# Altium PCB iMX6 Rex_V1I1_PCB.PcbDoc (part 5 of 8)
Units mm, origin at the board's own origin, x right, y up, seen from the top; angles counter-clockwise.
Board outline 70 x 40 mm, 12 copper layers (L1, L2, L3, L4, L5 (PWR), L6 (PWR), L7 (PWR), L8 (PWR), L9, L10, L11, L12), stack 1.566 mm thick; 473 components, 409 nets, 2294 pads, 1880 vias.
Unrouted connection lines stored in the file: 7.
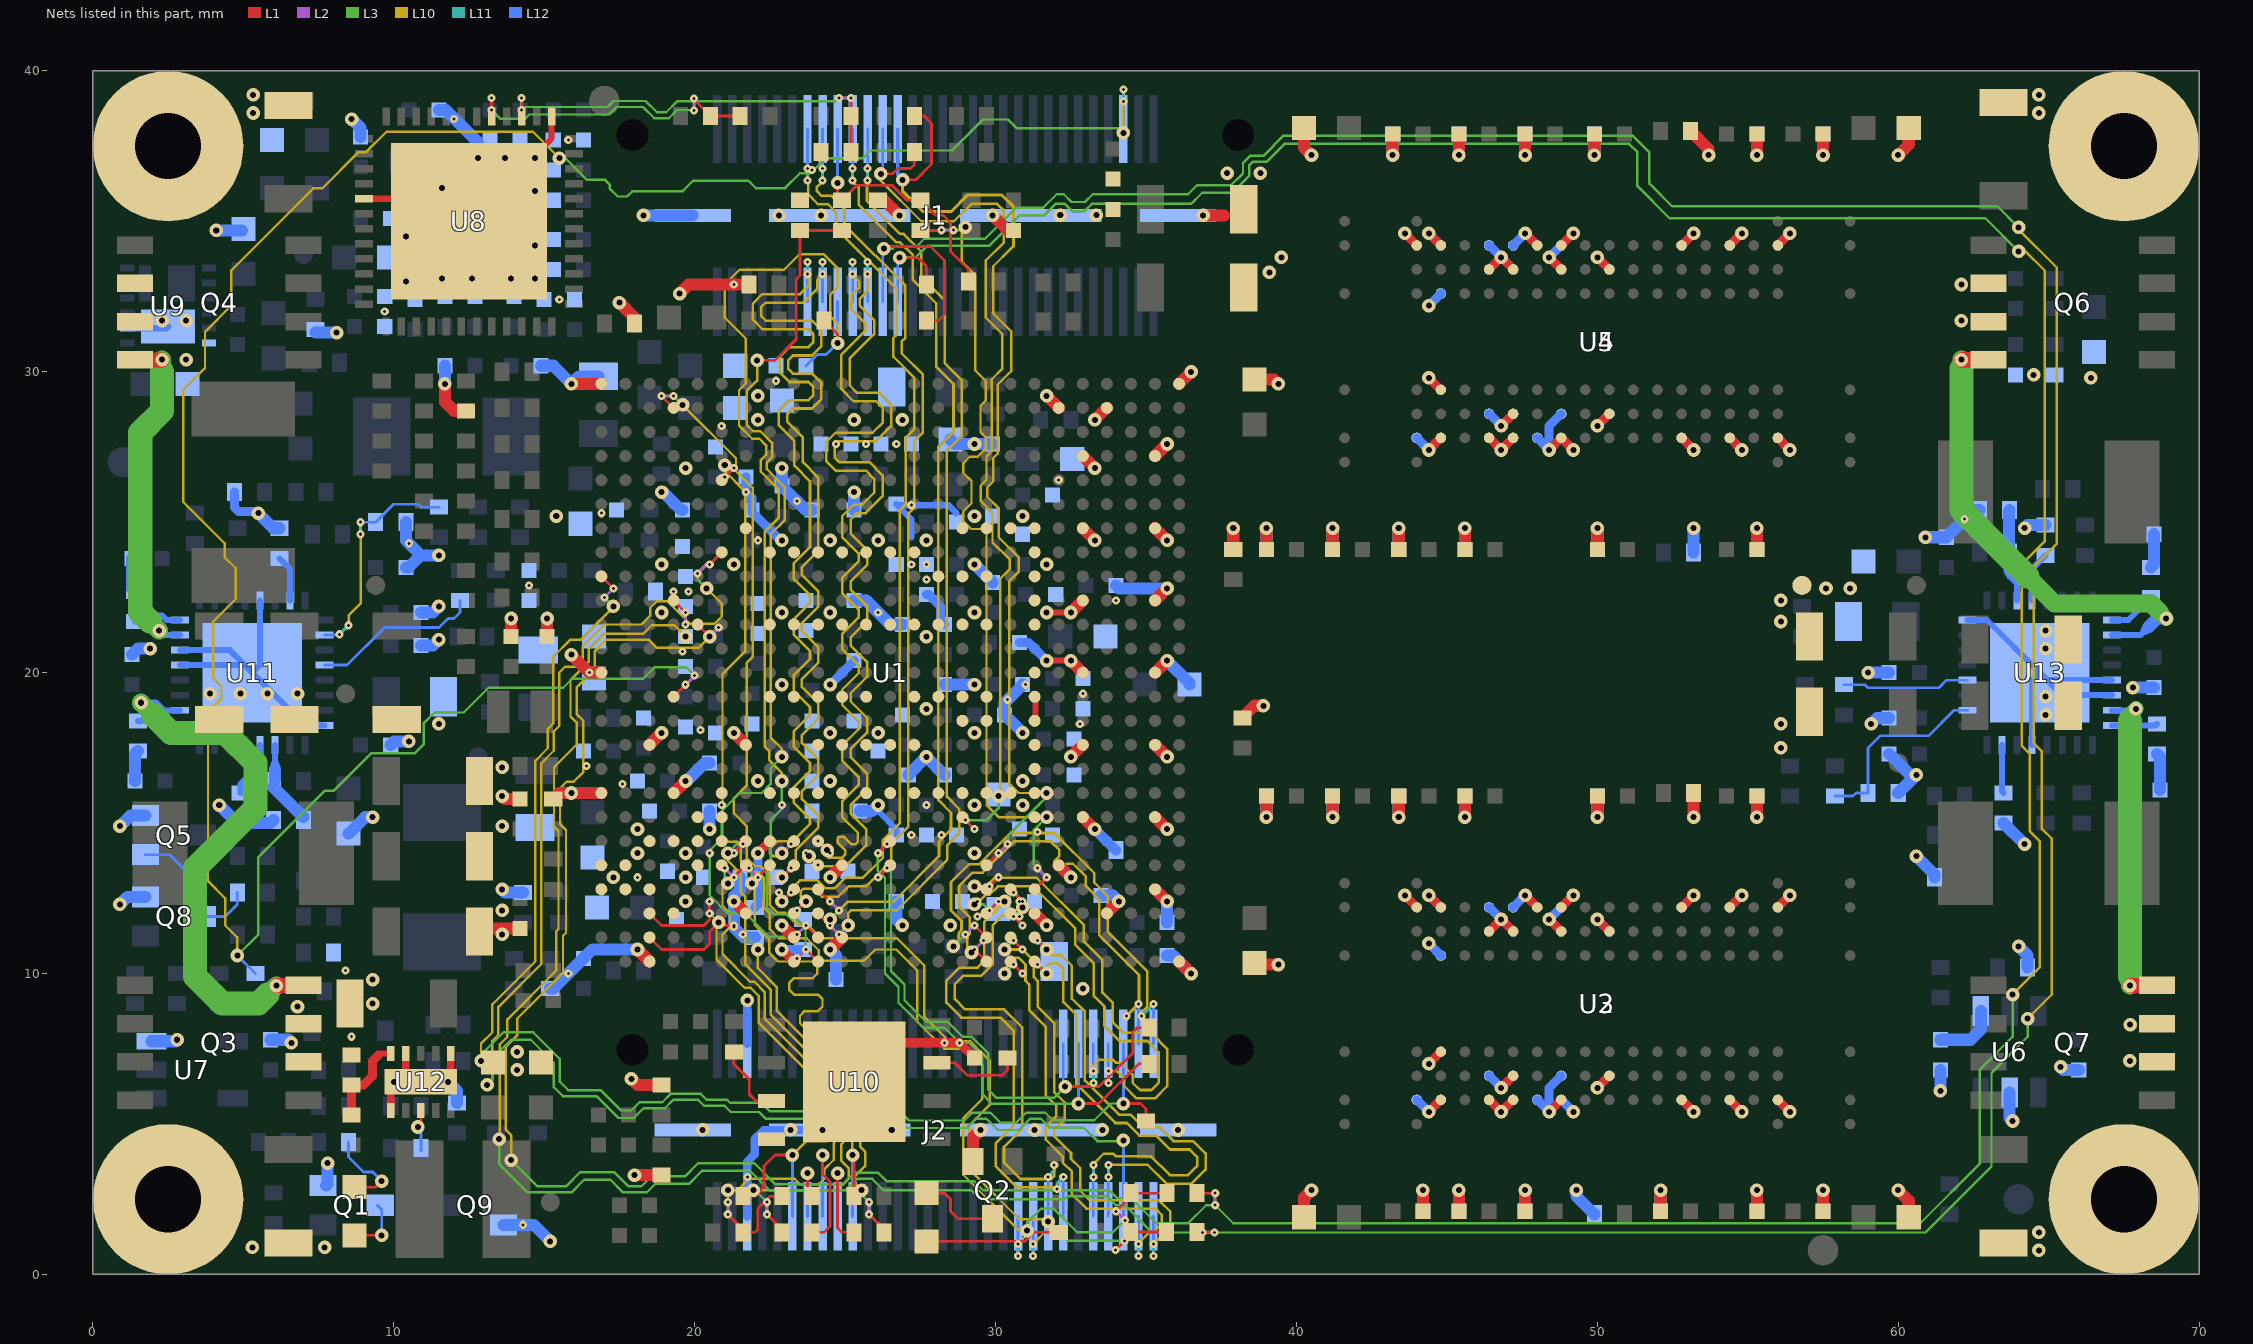
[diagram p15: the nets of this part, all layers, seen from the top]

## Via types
v1: diameter 0.45, hole 0.2, L1 to L12, tented both sides, 761 vias
v2: diameter 0.27, hole 0.1, L1 to L2, 305 vias
v3: diameter 0.27, hole 0.1, L2 to L3, 290 vias
v4: diameter 0.45, hole 0.2, L3 to L10, 196 vias
v5: diameter 0.27, hole 0.1, L11 to L12, 185 vias
v6: diameter 0.27, hole 0.1, L10 to L11, 142 vias
v7: diameter 0.45, hole 0.2, L3 to L10, tented both sides, 1 vias

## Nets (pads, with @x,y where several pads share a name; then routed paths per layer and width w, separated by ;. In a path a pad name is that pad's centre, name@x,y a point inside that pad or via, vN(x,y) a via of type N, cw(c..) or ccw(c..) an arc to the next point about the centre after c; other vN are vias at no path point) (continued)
FB1_2V5: R147.1 R150.2 U13.11 | length 3.1
  L12 w0.2: 63.7,23.3 63.7,23.2 63.95,22.95 U13.11@63.95,22.4
  L12 w0.3: 63.7,23.3 63.7,23.4
  L12 w0.4: 63.7,23.4 R147.1@63.7,24 63.675,24.025 63.675,25.375 R150.2@63.7,25.4
FB1_3V3: R123.1 R126.2 U11.11 | length 2.6
  L12 w0.2: 6.05,16.95 U11.11@6.05,17.6
  L12 w0.3: 6.05,16.8 6.05,16.95
  L12 w0.4: R123.1@6,16.2 R126.2@7,15.2 ; R123.1@6.05,16.45 6.05,16.8
FB_3V0_SNVS: R138.1 R139.2 U12.5 | length 3
  L1 w0.2: 9.5,7.3 9.55,7.35 U12.5@9.9,7.35
  L1 w0.3: R138.1@8.6,5.3 R139.2@8.6,6.3 9,6.3 9.3,6.6 9.3,7.1 9.5,7.3
GND: C1.2 C2.2 C3.2 C4.2 C5.2 C6.2 C7.2 C8.2 C9.2 C10.2 C11.2 C12.2 C13.2 C14.2 C15.2 C16.2 C17.2 C19.2 C20.2 C21.2 C22.2 C23.2 C24.2 C25.2 C26.2 C27.2 C28.2 C29.2 C30.2 C31.2 C32.2 C33.2 C34.2 C35.2 C36.2 C37.2 C38.2 C39.2 C40.2 C41.2 C42.2 C43.2 C44.2 C45.2 C46.2 C47.2 C48.2 C49.2 C50.2 C51.2 C52.2 C53.2 C54.2 C55.2 C56.2 C57.2 C58.2 C59.2 C60.2 C61.2 C62.2 C64.2 C68.2 C73.2 C74.1 C75.2 C76.2 C77.2 C78.2 C79.2 C80.2 C81.2 C82.2 C83.2 C84.2 C85.2 C86.2 C87.2 C88.2 C89.2 C90.2 C91.2 C92.2 C93.2 C94.2 C95.2 C96.2 C97.2 C98.2 C99.2 C100.2 C101.2 C102.2 C103.2 C104.2 C105.2 C106.2 C107.2 C108.2 C109.2 C110.2 C111.2 C112.2 C113.2 C114.2 C115.2 C116.2 C117.2 C118.2 C119.2 C120.2 C121.2 C122.2 C123.2 C124.2 C125.2 C126.2 C127.2 C128.2 C129.2 C130.2 C131.2 C132.2 C133.2 C134.2 C135.2 C136.2 C137.2 C138.2 C139.1 C140.2 C141.2 C142.2 C143.2 C144.2 C145.2 C146.2 C147.2 C148.2 C149.2 C150.2 C151.2 C152.2 C153.2 C154.2 C155.2 C156.2 C157.2 C158.2 C159.2 C160.2 C161.2 C162.2 C163.2 C164.2 C165.2 C166.2 C167.2 C168.2 C169.2 C170.2 C171.2 C172.2 C173.2 C174.2 C175.2 C176.2 C177.2 C178.2 C180.2 C181.2 C182.2 C183.2 C184.2 C185.2 C186.2 C187.2 C188.2 C189.2 C190.2 C191.2 C192.2 C193.2 C194.2 C195.2 C196.2 C197.2 C198.2 C199.2 C200.2 C201.2 C202.2 C203.2 C204.2 C205.2 C206.2 C207.2 C208.2 C209.2 C210.2 C213.2 C214.2 C215.2 C216.2 C217.2 C218.2 C219.2 C220.2 C221.2 C222.2 C223.2 C224.2 C225.2 C226.2 C227.2 C228.2 C229.2 C232.2 C233.2 C234.2 C235.2 C236.2 C237.2 C238.2 C239.2 C240.2 C241.2 C242.2 C243.2 C244.2 C245.2 C246.2 C247.2 C248.2 C249.2 J1.61 J1.62 J1.63 J1.64 J2.55 J2.56 J2.61 J2.62 J2.63 J2.64 MH1.1 MH2.1 MH3.1 MH4.1 Q1.2 Q2.2 Q3.2 Q3.3 Q4.2 Q4.3 Q5.2 Q6.2 Q6.3 Q7.2 Q7.3 Q8.2 Q9.2 R4.1 R5.1 R6.1 R7.1 R8.1 R9.1 R10.2 R12.1 R15.1 R16.1 R17.1 R20.1 R26.1 R30.1 R37.2 R56.1 R57.1 R58.1 R61.1 R67.1 R79.1 R84.2 R99.1 R101.1 R102.1 R124.2 R125.1 R126.1 R133.1 R136.1 R139.1 R143.1 R144.1 R148.2 R149.1 R150.1 R155.1 R158.1 TP10.1 U1.A4 U1.A5 U1.A8 U1.A13 U1.A25 U1.AA7 U1.AA10 U1.AA13 U1.AA16 U1.AA19 U1.AA22 U1.AB3 U1.AB24 U1.AD4 U1.AD7 U1.AD10 U1.AD13 U1.AD16 U1.AD19 U1.AD22 U1.AE1 U1.AE25 U1.B4 U1.B5 U1.C1 U1.C4 U1.C6 U1.C10 U1.D3 U1.D6 U1.D8 U1.E5 U1.E6 U1.E7 U1.F5 U1.F6 U1.F7 U1.F8 U1.G3 U1.G10 U1.G19 U1.H8 U1.H12 U1.H15 U1.H18 U1.J2 U1.J8 U1.J12 U1.J15 U1.J18 U1.K8 U1.K10 U1.K12 U1.K15 U1.K18 U1.L2 U1.L5 U1.L8 U1.L10 U1.L12 U1.L15 U1.L18 U1.M8 U1.M10 U1.M12 U1.M15 U1.M18 U1.N8 U1.N10 U1.N15 U1.N18 U1.P8 U1.P10 U1.P12 U1.P15 U1.P18 U1.R8 U1.R12 U1.R15 U1.R17 U1.T8 U1.T11 U1.T12 U1.T15 U1.T17 U1.T19 U1.U8 U1.U11 U1.U12 U1.U15 U1.U17 U1.U19 U1.V8 U1.V19 U1.W3 U1.W7 U1.W8 U1.W9 U1.W10 U1.W11 U1.W12 U1.W13 U1.W15 U1.W16 U1.W17 U1.W18 U1.W19 U1.Y5 U1.Y24 U2.A9 U2.B1 U2.B3 U2.B9 U2.D1 U2.D8 U2.E1 U2.E2 U2.E8 U2.F9 U2.G1 U2.G8 U2.G9 U2.J2 U2.J8 U2.M1 U2.M9 U2.P1 U2.P9 U2.T1 U2.T9 U3.A9 U3.B1 U3.B3 U3.B9 U3.D1 U3.D8 U3.E1 U3.E2 U3.E8 U3.F9 U3.G1 U3.G8 U3.G9 U3.J2 U3.J8 U3.M1 U3.M9 U3.P1 U3.P9 U3.T1 U3.T9 U4.A9 U4.B1 U4.B3 U4.B9 U4.D1 U4.D8 U4.E1 U4.E2 U4.E8 U4.F9 U4.G1 U4.G8 U4.G9 U4.J2 U4.J8 U4.M1 U4.M9 U4.P1 U4.P9 U4.T1 U4.T9 U5.A9 U5.B1 U5.B3 U5.B9 U5.D1 U5.D8 U5.E1 U5.E2 U5.E8 U5.F9 U5.G1 U5.G8 U5.G9 U5.J2 U5.J8 U5.M1 U5.M9 U5.P1 U5.P9 U5.T1 U5.T9 U6.2 U7.3 U8.13 U8.29 U8.49 U9.2 U9.12 U9.13 U10.4 U10.9 U11.8 U11.21 U11.22 U11.29 U11.33 U12.1 U12.4 U12.6 U12.11 U13.8 U13.21 U13.22 U13.29 U13.33 | length 250
  L1 w0.2: U8.29@9.01,35.75 U8.49@10.2,35.75 ; U8.49@14.65,37.15 15.25,37.75 U8.13@15.25,38.49 ; U1.W11@31.3,18.4 31.325,18.425 31.325,19.175 U1.W12@31.3,19.2 ; v1(31.7,20.4) v1(32.5,20.4) ; v1(31.7,22) v1(32.5,22)
  L1 w0.25: U12.6@9.9,5.35 9.9,6.3 v1(10,6.4) ; U12.11@10.4,6.2 U12.4@10.4,7.25 ; U12.11@11.9,6.4 U12.1@11.9,7.25
  L1 w0.3: U10.9@25.3,6.4 26.6,7.7 v2(28.8,7.7) C203.2@29.3,7.2 ; v1(43.6,12.6) U2.A9@44,12.2 ; v1(43.6,34.6) U4.A9@44,34.2 ; v1(44.4,5.4) U2.B1@44.8,5.8 ; v1(44.4,7) U2.B3@44.8,7.4 ; v1(44.4,12.6) U2.B9@44.8,12.2 ; v1(44.4,27.4) U4.B1@44.8,27.8 ; v1(44.4,29.8) U4.B3@44.8,29.4 ; v1(44.4,34.6) U4.B9@44.8,34.2 ; U2.D1@46.4,5.8 v1(46.8,5.4) U2.E1@47.2,5.8 ; U2.D8@46.4,11.4 v1(46.8,11.8) U2.E8@47.2,11.4 ; U4.D1@46.4,27.8 v1(46.8,27.4) U4.E1@47.2,27.8 ; U4.D8@46.4,33.4 v1(46.8,33.8) U4.E8@47.2,33.4 ; v1(46.8,6.2) U2.E2@47.2,6.6 ; v1(46.8,28.2) U4.E2@47.2,28.6 ; v1(47.6,12.6) U2.F9@48,12.2 ; v1(47.6,34.6) U4.F9@48,34.2 ; v1(48.4,5.4) U2.G1@48.8,5.8 ; v1(48.4,11.8) U2.G8@48.8,11.4 ; v1(48.4,27.4) U4.G1@48.8,27.8 ; v1(48.4,33.8) U4.G8@48.8,33.4 ; U2.G9@48.8,12.2 v1(49.2,12.6) ; U4.G1@48.8,27.8 v1(49.2,27.4) ; U4.G9@48.8,34.2 v1(49.2,34.6) ; v1(50,6.2) U2.J2@50.4,6.6 ; v1(50,11.8) U2.J8@50.4,11.4 ; v1(50,28.2) U4.J2@50.4,28.6 ; v1(50,33.8) U4.J8@50.4,33.4 ; U2.M1@52.8,5.8 v1(53.2,5.4) ; U2.M9@52.8,12.2 v1(53.2,12.6) ; U4.M1@52.8,27.8 v1(53.2,27.4) ; U4.M9@52.8,34.2 v1(53.2,34.6) ; U2.P1@54.4,5.8 v1(54.8,5.4) ; U2.P9@54.4,12.2 v1(54.8,12.6) ; U4.P1@54.4,27.8 v1(54.8,27.4) ; U4.P9@54.4,34.2 v1(54.8,34.6) ; U2.T1@56,5.8 v1(56.4,5.4) ; U2.T9@56,12.2 v1(56.4,12.6) ; U4.T1@56,27.8 v1(56.4,27.4) ; U4.T9@56,34.2 v1(56.4,34.6)
  L1 w0.4: v1(11.7,29.6) 11.7,29 12,28.7 R99.1@12.4,28.7 ; C215.2@13.2,11.5 C84.2@14.2,11.5 ; v1(13.6,15.9) 13.7,15.8 C83.2@14.2,15.8 ; C86.2@13.9,21.2 v1(13.9,21.8) ; C85.2@15.1,21.2 v1(15.1,21.8) ; R37.2@15.3,15.8 15.5,16 v1(15.9,16) U1.A8@16.9,16 ; v1(15.9,20.6) v2(16.5,20) U1.A13@16.9,20 ; v1@15.9,29.6 U1.A25@16.9,29.6 ; v1(17.5,32.3) 18,31.8 R84.2@18,31.6 ; v1(17.9,6.5) 18.1,6.3 R16.1@18.9,6.3 ; v1(18,3.3) R17.1@18.9,3.3 ; v1(18.1,10.8) U1.C1@18.5,10.4 ; U1.C10@18.5,17.6 v1(18.9,18) ; U1.D8@19.3,16 v1(19.7,16.4) ; v1(19.5,32.6) 19.8,32.9 v2(21.3,32.9) R143.1@21.8,32.9 ; v1(21.3,12.4) U1.G3@21.7,12 ; v1(21.3,18) U1.G10@21.7,17.6 ; v1(22.9,11.6) U1.J2@23.3,11.2 ; v1(24.5,10.8) U1.L2@24.9,11.2 ; v1(24.5,13.2) U1.L5@24.9,13.6 ; R144.1@26.1,35.7 26.3,35.7 v1(26.8,35.2) ; Q2.2@29.25,3.75 29.25,4.55 v1(29.5,4.8) ; v1(29.9,35.2) 30.4,34.7 C242.2@30.6,34.7 ; U1.W3@31.3,12 v1(31.7,11.6) ; v1(31.7,29.2) U1.Y24@32.1,28.8 ; U1.Y5@32.1,13.6 v1(32.5,13.2) ; v1(32.5,17.2) U1.AA10@32.9,17.6 ; v1(32.5,20.4) U1.AA13@32.9,20 ; v1(32.5,22) U1.AA16@32.9,22.4 ; U1.AA7@32.9,15.2 v1(33.3,14.8) ; U1.AA19@32.9,24.8 v1(33.3,24.4) ; U1.AA22@32.9,27.2 v1(33.3,26.8) ; v1(33.3,28.4) U1.AB24@33.7,28.8 ; U1.AB3@33.7,12 v1(34.1,12.4) ; U1.AD4@35.3,12.8 v1(35.7,12.4) ; U1.AD7@35.3,15.2 v1(35.7,14.8) ; U1.AD10@35.3,17.6 v1(35.7,17.2) ; U1.AD13@35.3,20 v1(35.7,20.4) ; U1.AD16@35.3,22.4 v1(35.7,22.8) ; U1.AD19@35.3,24.8 v1(35.7,24.4) ; U1.AD22@35.3,27.2 v1(35.7,27.6) ; U1.AE1@36.1,10.4 v1(36.5,10) ; U1.AE25@36.1,29.6 v1(36.5,30) ; v1(36.9,35.2) 37.6,35.2 ; R10.2@37.9,24.1 v1(37.9,24.8) ; R6.1@38.2,18.5 38.6,18.9 v1@38.8,18.9 ; C12.2@38.6,10.35 38.65,10.3 v1(39.4,10.3) ; C17.2@38.6,29.75 39.25,29.75 v1(39.4,29.6) ; v1(39,15.2) C26.2@39,15.9 ; C39.2@39,24.1 v1(39,24.8) ; C14.2@40.25,1.9 40.25,2.55 v1(40.5,2.8) ; C15.2@40.25,38.1 40.25,37.45 v1(40.5,37.2) ; v1(41.2,15.2) C24.2@41.2,15.9 ; C40.2@41.2,24.1 v1(41.2,24.8) ; v1(43.2,37.2) C36.2@43.2,37.9 ; v1(43.4,15.2) C25.2@43.4,15.9 ; C31.2@43.4,24.1 v1(43.4,24.8) ; C27.2@44.2,2.1 v1(44.2,2.8) ; C28.2@45.4,2.1 v1(45.4,2.8) ; v1(45.4,37.2) C37.2@45.4,37.9 ; v1(45.6,15.2) C23.2@45.6,15.9 ; C33.2@45.6,24.1 v1(45.6,24.8) ; C29.2@47.6,2.1 v1(47.6,2.8) ; v1(47.6,37.2) C34.2@47.6,37.9 ; v1(49.9,37.2) C8.2@49.9,37.9 ; v1(50,15.2) C3.2@50,15.9 ; C9.2@50,24.1 v1(50,24.8) ; C4.2@52.1,2.1 v1(52.1,2.8) ; R8.1@53.1,38 53.7,37.4 v1(53.7,37.2) ; v1(53.2,15.2) R4.1@53.2,16 ; C30.2@55.3,2.1 v1(55.3,2.8) ; v1(55.3,15.2) C22.2@55.3,15.9 ; C32.2@55.3,24.1 v1(55.3,24.8) ; v1(55.3,37.2) C38.2@55.3,37.9 ; C21.2@57.5,2.1 v1(57.5,2.8) ; v1(57.5,37.2) C35.2@57.5,37.9 ; v1(60,2.8) 60.35,2.45 C13.2@60.35,1.9 ; v1(60,37.2) 60.35,37.55 C16.2@60.35,38.1
  L12 w0.2: U11.21@2.9,20.25 U11.33@5.05,20.25 ; U11.22@2.9,20.75 4.55,20.75 U11.33@5.05,20.25 ; U11.29@5.55,22.4 5.55,20.25 U11.33@5.3,20 ; U11.8@7.7,18.25 7.05,18.25 U11.33@5.3,20 ; v1(26.1,15.6) 26.1,15.401 26.7,14.801 C107.2@26.7,14.6 ; U13.8@62.3,21.75 62.95,21.75 U13.33@64.7,20 ; U13.29@64.45,17.6 64.45,19.75 U13.33@64.7,20 ; U13.22@67.1,19.25 65.45,19.25 U13.33@64.95,19.75 ; U13.21@67.1,19.75 U13.33@64.95,19.75 ; U11.33@5.05,20.25 U11.33@5.3,20 ; U13.33@64.7,20 U13.33@64.95,19.75
  L12 w0.22: U9.2@1.14,31.45 2.448,31.45 U9.13@2.5,31.501 ; C130.2@26.7,25.6 C130.2@26.735,25.565 ; 27.2,24.5 27.2,25.1 C130.2@26.735,25.565 ; 28.7,25.3 28.435,25.565 C130.2@26.735,25.565
  L12 w0.28: J2.55@21.75,1.93 21.75,3.75 21.994,3.994 21.994,4.494 22.3,4.8 J2.63@24.825,4.8 ; J2.56@21.75,7.67 v1(21.75,9.108)
  L12 w0.3: R136.1@4.7,26 4.7,25.5 4.85,25.35 5.45,25.35 v1(5.5,25.3) ; C125.2@21.7,26.5 v5(21.7,26) 21.9,25.8 C122.2@21.9,25.4 21.9,25.346 22.846,24.4 v1(22.9,24.4) ; v1(24.5,19.6) C94.2@25.3,20.4 ; C113.2@27.7,22.6 27.772,22.6 28.175,22.197 28.175,21.725 C97.2@28.3,21.6 ; C117.2@30.8,21 31.1,21 v1(31.7,20.4) ; U3.A9@44,5.8 v1(44.4,5.4) U3.B9@44.8,5.8 ; U5.A9@44,27.8 v1(44.4,27.4) U5.B9@44.8,27.8 ; v1(44.4,11) U3.B3@44.8,10.6 ; v1(44.4,12.6) U3.B1@44.8,12.2 ; v1(44.4,32.2) U5.B3@44.8,32.6 ; v1(44.4,34.6) U5.B1@44.8,34.2 ; U3.D8@46.4,6.6 v1(46.8,6.2) U3.E8@47.2,6.6 ; U3.D1@46.4,12.2 U3.E2@47.2,11.4 ; U5.D8@46.4,28.6 v1(46.8,28.2) U5.E8@47.2,28.6 ; U5.D1@46.4,34.2 v1(46.8,33.8) U5.E2@47.2,33.4 ; U3.E1@47.2,12.2 v1(47.6,12.6) ; U5.E1@47.2,34.2 v1(47.6,34.6) ; U3.F9@48,5.8 v1(48.4,5.4) 48.4,6.2 U3.G8@48.8,6.6 ; U5.F9@48,27.8 v1(48.4,27.4) 48.4,28.2 U5.G8@48.8,28.6 ; v1(48.4,11.8) U3.G1@48.8,12.2 ; v1(48.4,33.8) U5.G1@48.8,34.2 ; U3.G9@48.8,5.8 v1(49.2,5.4) ; U5.G9@48.8,27.8 v1(49.2,27.4) ; v1(50,6.2) U3.J8@50.4,6.6 ; v1(50,11.8) U3.J2@50.4,11.4 ; v1(50,28.2) U5.J8@50.4,28.6 ; v1(50,33.8) U5.J2@50.4,33.4 ; U3.M9@52.8,5.8 v1(53.2,5.4) ; U3.M1@52.8,12.2 v1(53.2,12.6) ; U5.M9@52.8,27.8 v1(53.2,27.4) ; U5.M1@52.8,34.2 v1(53.2,34.6) ; U3.P9@54.4,5.8 v1(54.8,5.4) ; U3.P1@54.4,12.2 v1(54.8,12.6) ; U5.P9@54.4,27.8 v1(54.8,27.4) ; U5.P1@54.4,34.2 v1(54.8,34.6) ; U3.T9@56,5.8 v1(56.4,5.4) ; U3.T1@56,12.2 v1(56.4,12.6) ; U5.T9@56,27.8 v1(56.4,27.4) ; U5.T1@56,34.2 v1(56.4,34.6)
  L12 w0.35: v1(33.3,14.8) R7.1@34,14.1
  L12 w0.4: v1(0.9,12.3) 1.15,12.55 Q8.2@1.75,12.55 ; v1(0.9,14.9) 1.25,15.25 Q5.2@1.75,15.25 ; C206.2@1.3,20.6 1.5,20.8 v1(1.9,20.8) ; U7.3@1.95,7.75 2.75,7.75 v1(2.8,7.8) ; v1(4.1,34.7) C178.2@4.95,34.7 ; v1(4.2,15.6) R125.1@4.8,15 ; R125.1@4.9,15 5.9,15 R126.1@6,15.1 ; v1(5.5,25.3) 6,24.8 R124.2@6.2,24.8 ; C89.2@5.9,7.8 6.5,7.8 v1(6.6,7.7) ; R101.1@7.4,31.3 v1(8.1,31.3) ; Q1.2@7.75,2.95 7.8,3 v1(7.8,3.7) ; C204.2@8.5,14.65 9.05,15.2 v1(9.3,15.2) ; v1(8.6,38.4) 8.9,38.1 C184.2@8.9,37.8 ; C205.2@9.9,17.6 10.014,17.714 v1(10.5,17.714) ; C219.2@10.4,23.5 10.5,23.5 10.9,23.9 ; R133.1@10.4,25 10.4,24.4 10.9,23.9 ; C218.2@10.9,20.9 11.3,20.9 v1(11.5,21.1) ; C207.2@10.9,22 11.3,22 v1(11.5,22.2) ; v1(11.5,23.9) 10.9,23.9 ; C249.2@11.5,38.7 11.727,38.7 12.8,37.627 v1(12.8,37.1) ; v1(11.6,36.1) C186.2@12.3,35.4 ; v1(11.7,29.6) C176.2@11.7,30.2 ; v1(11.8,6.4) 12.1,6.1 R58.1@12.1,5.7 ; C186.2@12.35,35.4 C186.2@12.45,35.4 ; v1(13.6,12.8) 13.7,12.7 R79.1@14.3,12.7 ; Q9.2@13.65,1.65 14.65,1.65 v1(15.2,1.1) ; C175.2@14.9,30.2 15.3,30.2 v1(15.9,29.6) 16.15,29.85 C148.2@16.8,29.85 ; R15.1@15.2,9.5 15.3,9.5 C244.2@16.3,10.5 16.6,10.8 v1(18.1,10.8) ; v1(18.3,35.2) J1.64@19.935,35.2 ; v1(18.9,26) 18.958,26 19.558,25.4 C152.2@19.6,25.4 ; v1(19.7,16.4) 19.735,16.4 20.335,17 C139.1@20.5,17 ; v1(20.5,14.8) C143.2@20.5,15.4 ; C61.2@21.5,13.2 21.5,12.774 21.3,12.574 v1(21.3,12.4) v5(21.3,11.542) 21.642,11.2 R61.1@22,11.2 ; v1(22.9,26.8) C131.2@22.9,26.2 23.7,25.4 C134.2@23.9,25.4 ; v1(24.5,10.8) 24.7,10.6 C1.2@24.7,9.8 ; C124.2@25.3,22.4 25.7,22.4 26.5,21.6 C95.2@26.9,21.6 ; C133.2@25.3,25.4 v1(25.3,26) ; C90.2@25.5,15.4 25.9,15.4 v1(26.1,15.6) ; C76.2@26.7,12.4 26.7,11.8 v1(26.9,11.6) ; C116.2@27.1,16.6 v1(27.7,17.2) C115.2@28.3,16.6 ; C105.2@28.3,19.6 v1(29.3,19.6) ; C129.2@28.5,27.75 28.65,27.6 v1(29.3,27.6) C160.2@29.9,27.6 ; v1(29.3,23.6) C114.2@29.9,23 ; v1(30.9,18) C102.2@30.3,18.6 30.3,19 C112.2@30.9,19.6 ; C243.2@33.5,12.6 33.9,12.6 v1(34.1,12.4) ; C171.2@34,22.9 34.1,22.8 v1(35.7,22.8) ; C245.2@35.7,10.6 35.9,10.6 v1(36.5,10) ; C7.2@35.7,11.7 v1(35.7,12.4) ; v1(35.7,20.4) 36.45,19.65 C172.2@36.45,19.6 ; v1(39,15.2) C46.2@39,15.9 ; C60.2@39,24.1 v1(39,24.8) ; v1(41.2,15.2) C43.2@41.2,15.9 ; C51.2@41.2,24.1 v1(41.2,24.8) ; v1(43.2,37.2) C57.2@43.2,37.9 ; v1(43.4,15.2) C45.2@43.4,15.9 ; C53.2@43.4,24.1 v1(43.4,24.8) ; C47.2@44.2,2.1 v1(44.2,2.8) ; C49.2@45.4,2.1 v1(45.4,2.8) ; v1(45.4,37.2) C56.2@45.4,37.9 ; v1(45.6,15.2) C44.2@45.6,15.9 ; C52.2@45.6,24.1 v1(45.6,24.8) ; C48.2@47.6,2.1 v1(47.6,2.8) ; v1(47.6,37.2) C59.2@47.6,37.9 ; v1(49.3,2.8) 49.3,2.6 R5.1@49.9,2 ; v1(49.9,37.2) C10.2@49.9,37.9 ; v1(50,15.2) C5.2@50,15.9 ; C11.2@50,24.1 v1(50,24.8) ; C6.2@52.1,2.1 v1(52.1,2.8) ; R9.1@53.2,24 v1(53.2,24.8) ; C50.2@55.3,2.1 v1(55.3,2.8) ; v1(55.3,15.2) C42.2@55.3,15.9 ; C54.2@55.3,24.1 v1(55.3,24.8) ; v1(55.3,37.2) C58.2@55.3,37.9 ; C41.2@57.5,2.1 v1(57.5,2.8) ; v1(57.5,37.2) C55.2@57.5,37.9 ; v1(59,20) C237.2@59.7,20 ; v1(59.1,18.3) 59.3,18.5 C226.2@59.7,18.5 ; C238.2@59.7,17.3 60.4,16.6 v1(60.6,16.6) R155.1@60,16 ; v1(60.6,13.9) 61.2,13.3 R158.1@61.2,13.2 ; v1(60.9,24.5) C224.2@61.6,24.5 62.5,25.4 R150.1@62.7,25.4 ; v1(61.4,6.1) C88.2@61.4,6.8 ; R148.2@63.5,15 v1(64.2,14.3) ; U6.2@63.7,6.05 63.7,5.2 v1(63.8,5.1) ; v1(64,10.9) 64.3,10.6 R67.1@64.3,10.2 ; v1(64.2,24.8) 64.3,24.9 R149.1@64.9,24.9 ; v1(65.4,6.9) 65.5,6.8 C87.2@66,6.8 ; v1(67.8,19.5) C225.2@68.5,19.5
  other v1: 64.675,0.8 5.3,0.9 7.7,0.9 64.675,1.4 20.263,4.805 23.187,4.805 24.25,4.805 26.55,4.805 31.3,4.8 33.55,4.805 36.065,4.8 14.1,6.8 67.7,7.1 14.1,7.4 67.705,8.3 6.8,8.9 9.3,9 32.9,9.5 9.3,9.8 13.6,11.3 28.5,11.6 13.6,12.1 19.7,12.4 17.3,13.2 19.7,13.2 18.1,14 19.7,14 29.3,14 18.1,14.8 13.6,14.9 29.3,15.6 30.9,15.6 22.1,16.4 24.5,16.4 30.9,16.4 13.6,16.85 56.1,17.5 24.5,18 26.1,18 29.3,18 11.5,18.3 56.1,18.3 64.9,18.6 27.7,18.8 38.9,18.9 64.9,19.2 3.9,19.3 4.9,19.3 5.8,19.3 6.8,19.3 22.9,19.6 64.9,20.8 27.7,21.2 64.9,21.4 56.1,21.7 18.9,22 22.9,22 24.5,22 29.3,22 56.1,22.4 57.6,22.8 58.4,22.8 18.9,23.6 21.3,23.6 31.7,23.6 24.5,24.4 26.1,24.4 27.7,24.4 15.4,25.2 29.3,25.2 30.9,25.2 19.7,26.8 22.1,28.4 25.3,28.4 26.9,28.4 22.1,29.2 66.4,29.8 64.5,29.9 3.1,30.4 2.3,31.7 3.1,31.7 62.1,31.7 62.1,32.9 10.4,33 11.6,33.1 12.6,33.1 13.9,33.1 14.7,33.1 39.1,33.3 39.5,33.8 14.7,34.2 10.4,34.5 22.8,35.2 24.2,35.2 32.15,35.205 33.35,35.205 14.7,36 37.7,36.6 38.8,36.6 13.7,37.1 14.7,37.1 5.325,38.6 64.675,38.6 5.325,39.2 64.675,39.2
  other v2: 28.3,7.7 8.6,7.9 18.1,13.2 20.5,14 20.9,15.6 22.9,15.6 27.7,15.6 31,19.6 26.1,22 27.7,23.6 22.1,24.4 23.9,36.7
  other v5: 14.3,1.65 21.75,3.243 15.8,10 8.4,10.1 29.4,11.9 30.8,11.9 29.4,12.4 30.8,12.4 22.8,12.7 27.2,14.6 28.2,14.6 31.4,14.7 17.6,16.3 16.4,16.9 20.2,18.1 32.8,18.3 30.4,19.1 32.9,19.3 19.6,20.7 26.1,22 34,22.4 19.3,22.7 19.8,22.7 14.5,22.9 27.7,23.1 27.2,23.6 10.5,24.3 62.2,25.1 16.9,25.3 27.2,25.565 23.4,25.7 32.1,26.4 24.7,27.6 25.7,27.6 26.7,27.6 20.9,28.2 22.7,29.7 9.7,32 15.5,32.4 15.8,37.7 12,38.4
HDMI_CEC: R25.1 U1.W4 | length 27.5
  L1 w0.093: R25.1@27.6,34.7 28.195,34.7 v2(28.2,34.705) ; U1.W4@31.3,12.8 v2(31.7,13.2)
  L2 w0.1: v2(28.2,34.705) v3(28.6,34.705) ; v3(31.4,13.5) v2(31.7,13.2)
  L3 w0.08: v3(28.6,34.705) 28.9,34.705 v4(29,34.805) ; v3(31.4,13.5) 31.275,13.625 31.275,14.775 v4(31.7,15.2)
  L10 w0.08: v4(29,34.805) 28.875,34.68 28.875,33.665 29.325,33.215 29.325,30.045 29.675,29.695 29.675,29.045 29.5,28.87 29.5,28 29.675,27.825 29.675,27.445 29.405,27.175 29.145,27.175 28.925,26.955 28.925,26.645 29.2,26.37 29.2,25.63 28.925,25.355 28.925,25.045 29.195,24.775 29.525,24.775 29.7,24.6 29.7,15.6 30.1,15.2 v4(31.7,15.2)
HDMI_CEC_IN: J1.44 R22.1 R24.2 R25.2 | length 9
  L1 w0.093: v1(24.75,36.28) 24.75,35.85 R24.2@24.9,35.7 25.4,36.2 26.562,36.2 27.062,35.7 R25.2@27.5,35.7 27.995,35.205 28.25,35.205 28.5,34.955 28.5,34 29.1,33.4 R22.1@29.1,33
  L12 w0.093: v1(24.75,36.28) J1.44@24.75,38.07
HDMI_CLK_N: J1.45 U1.J5 | length 32.2
  L1 w0.09: v2(22.9,13.2) U1.J5@23.3,13.6
  L2 w0.1: v2(22.9,13.2) v3(23.2,13.5)
  L3 w0.085: v2(22.9,13.2) v3(23.2,13.5)
  L10 w0.085: v2(22.9,13.2) 23.363,13.663 23.363,14.103 24.114,14.854 24.114,15.252 23.566,15.8 23.566,16.066 24.114,16.614 24.114,17.112 23.566,17.66 23.566,17.926 24.114,18.474 24.114,18.972 23.566,19.52 23.566,19.786 24.114,20.334 24.114,20.832 23.566,21.38 23.566,21.646 24.114,22.194 24.114,22.692 23.566,23.24 23.566,23.506 24.114,24.054 24.114,26.476 23.595,26.995 23.595,27.817 23.08,28.332 23.08,28.598 23.262,28.78 23.9,28.78 24.214,29.094 24.214,29.626 23.9,29.94 23.262,29.94 23.112,30.09 23.112,30.39 23.262,30.54 23.9,30.54 24.214,30.854 24.214,31.386 23.9,31.7 22.362,31.7 22.212,31.85 22.212,32.15 22.362,32.3 23.616,32.3 24.08,32.764 24.08,33.046 24.25,33.216 v6(24.25,33.242)
  L11 w0.1: v6(24.25,33.242) v5(24.25,33.642)
  L12 w0.09: J1.45@24.25,32.33 v5(24.25,33.642)
  other v4: 22.9,13.2
HDMI_CLK_P: J1.47 U1.J6 | length 32.2
  L1 w0.09: v4(22.9,14) U1.J6@23.3,14.4
  L2 w0.1: v4(22.9,14) v3(23.2,14.3)
  L3 w0.085: v4(22.9,14) v3(23.2,14.3)
  L10 w0.085: v4(22.9,14) 22.8,13.9 22.6,13.9 22.5,14 22.5,14.15 22.75,14.4 23.264,14.4 23.834,14.97 23.834,15.136 23.286,15.684 23.286,16.182 23.834,16.73 23.834,16.996 23.286,17.544 23.286,18.042 23.834,18.59 23.834,18.856 23.286,19.404 23.286,19.902 23.834,20.45 23.834,20.716 23.286,21.264 23.286,21.762 23.834,22.31 23.834,22.576 23.286,23.124 23.286,23.622 23.834,24.17 23.834,26.36 23.315,26.879 23.315,27.701 22.8,28.216 22.8,28.714 23.146,29.06 23.784,29.06 23.934,29.21 23.934,29.51 23.784,29.66 23.146,29.66 22.832,29.974 22.832,30.506 23.146,30.82 23.784,30.82 23.934,30.97 23.934,31.27 23.784,31.42 22.246,31.42 21.932,31.734 21.932,32.266 22.246,32.58 23.5,32.58 23.8,32.88 23.8,33.192 v6(23.75,33.242)
  L11 w0.1: v6(23.75,33.242) v5(23.75,33.642)
  L12 w0.09: J1.47@23.75,32.33 v5(23.75,33.642)
  other v2: 22.9,14
HDMI_D0_N: J1.39 U1.K5 | length 32.1
  L1 w0.09: v2(23.7,14) v3(24.1,13.6)
  L2 w0.1: v2(23.7,14) v3(24.1,13.6)
  L3 w0.085: v4(23.8,13.9) v3(24.1,13.6)
  L10 w0.085: v4(23.8,13.9) 24.132,13.568 25.013,13.568 25.7,14.254 25.7,14.8 25.182,15.318 25.182,15.596 25.73,16.144 25.73,16.642 25.182,17.19 25.182,17.456 25.73,18.004 25.73,18.502 25.182,19.05 25.182,19.316 25.73,19.864 25.73,20.362 25.182,20.91 25.182,21.176 25.73,21.724 25.73,22.222 25.182,22.77 25.182,23.036 25.73,23.584 25.73,24.082 25.182,24.63 25.182,25.082 25.4,25.3 25.68,25.3 26.244,25.864 26.244,26.556 25.806,26.994 24.802,26.994 24.652,27.144 24.652,27.544 24.802,27.694 26.03,27.694 26.532,28.197 26.532,28.916 26.148,29.3 25.4,29.3 25.148,29.552 25.148,30.437 25.964,31.254 25.964,31.716 25.48,32.2 25.48,32.414 25.75,32.684 v6(25.75,33.242)
  L11 w0.1: v6(25.75,33.242) v5(25.75,33.642)
  L12 w0.09: J1.39@25.75,32.33 v5(25.75,33.642)
HDMI_D0_P: J1.41 U1.K6 | length 32.1
  L1 w0.09: v3(24.1,14.4) v2(24.5,14)
  L2 w0.1: v3(24.1,14.4) v2(24.5,14)
  L3 w0.085: v3(24.1,14.4) v4(24.4,14.1)
  L10 w0.085: v4(24.4,14.1) 24.4,13.898 24.45,13.848 24.897,13.848 25,13.95 25,14.1 24.75,14.35 24.75,14.5 24.8,14.55 24.95,14.55 25.2,14.3 25.35,14.3 25.42,14.37 25.42,14.684 24.902,15.202 24.902,15.712 25.45,16.26 25.45,16.526 24.902,17.074 24.902,17.572 25.45,18.12 25.45,18.386 24.902,18.934 24.902,19.432 25.45,19.98 25.45,20.246 24.902,20.794 24.902,21.292 25.45,21.84 25.45,22.106 24.902,22.654 24.902,23.152 25.45,23.7 25.45,23.966 24.902,24.514 24.902,25.198 25.284,25.58 25.564,25.58 25.964,25.98 25.964,26.44 25.69,26.714 24.686,26.714 24.372,27.028 24.372,27.66 24.686,27.974 25.914,27.974 26.252,28.312 26.252,28.8 26.032,29.02 25.284,29.02 24.868,29.437 24.868,30.553 25.684,31.37 25.684,31.6 25.2,32.084 25.2,32.53 25.47,32.8 25.47,32.996 25.25,33.216 v6(25.25,33.242)
  L11 w0.1: v6(25.25,33.242) v5(25.25,33.642)
  L12 w0.09: J1.41@25.25,32.33 v5(25.25,33.642)
HDMI_D1_N: J1.46 U1.J3 | length 32.1
  L1 w0.09: U1.J3@23.3,12 v4(23.7,12.4)
  L2 w0.1: v3(23.4,12.1) v4(23.7,12.4)
  L3 w0.085: v3(23.4,12.1) v4(23.7,12.4)
  L10 w0.085: v4(23.7,12.4) 23.523,12.577 23.523,12.727 23.616,12.82 23.964,12.82 24.232,12.552 24.768,12.552 25.116,12.9 25.7,12.9 26.532,13.732 26.532,14.317 27.1,14.884 27.1,25.284 27.3,25.484 27.3,27.704 27.582,27.986 27.582,29.914 26.88,30.616 26.88,31 27,31.12 27,32.86 24.98,34.88 24.98,35.416 24.548,35.848 24.216,35.848 24.06,36.004 24.06,36.14 24.25,36.331 v6(24.25,36.357)
  L11 w0.1: v6(24.25,36.357) v5(24.25,36.758)
  L12 w0.09: v5(24.25,36.758) J1.46@24.25,38.07
  other v2: 23.7,12.4
HDMI_D1_P: J1.48 U1.J4 | length 32.1
  L1 w0.09: v2(22.9,12.4) U1.J4@23.3,12.8
  L2 w0.1: v2(22.9,12.4) v3(23.2,12.7)
  L3 w0.085: v2(22.9,12.4) v3(23.2,12.7)
  L10 w0.085: v2(22.9,12.4) 23.243,12.743 23.243,12.843 23.5,13.1 24.08,13.1 24.348,12.832 24.652,12.832 25,13.18 ; v6(23.75,36.357) 23.78,36.328 23.78,35.888 24.1,35.568 24.432,35.568 24.7,35.3 24.7,34.764 26.72,32.744 26.72,31.236 26.6,31.116 26.6,30.5 27.302,29.798 27.302,28.102 27.02,27.82 27.02,25.6 26.82,25.4 26.82,15 26.252,14.433 26.252,13.848 25.584,13.18 25,13.18
  L11 w0.1: v6(23.75,36.357) v5(23.75,36.758)
  L12 w0.09: v5(23.75,36.758) J1.48@23.75,38.07
  other v4: 22.9,12.4
HDMI_D2_N: J1.40 U1.K3 | length 32.1
  L1 w0.09: U1.K3@24.1,12 v2(24.5,11.6)
  L2 w0.1: v2(24.5,11.6) v3(24.8,11.3)
  L3 w0.085: v3(24.8,11.3) v4(25.1,11.6)
  L10 w0.085: v4(25.1,11.6) 25.1,12.004 25.196,12.1 26.716,12.1 28.4,13.784 28.4,14.266 28.8,14.666 28.8,15.46 28.38,15.88 28.38,27.384 28.882,27.886 28.882,29.714 28.308,30.288 28.308,32.392 27.53,33.17 27.53,33.991 26.941,34.58 26.825,34.58 25.728,35.677 25.728,36.335 v6(25.75,36.357)
  L11 w0.1: v6(25.75,36.357) v5(25.75,36.758)
  L12 w0.09: v5(25.75,36.758) J1.40@25.75,38.07
HDMI_D2_P: J1.42 U1.K4 | length 32.1
  L1 w0.09: U1.K4@24.1,12.8 v2(24.5,12.4)
  L2 w0.1: v2(24.5,12.4) v3(24.8,12.1)
  L3 w0.085: v4(24.5,11.8) v3(24.8,12.1)
  L10 w0.085: v4(24.5,11.8) 25.08,12.38 26.6,12.38 28.12,13.9 28.12,14.382 28.52,14.782 28.52,15.344 28.1,15.764 28.1,27.5 28.602,28.002 28.602,29.598 28.028,30.172 28.028,32.277 27.25,33.054 27.25,33.875 26.825,34.3 26.709,34.3 25.448,35.561 25.448,36.133 25.25,36.331 v6(25.25,36.357)
  L11 w0.1: v6(25.25,36.357) v5(25.25,36.758)
  L12 w0.09: v5(25.25,36.758) J1.42@25.25,38.07
HDMI_DDC: R24.1 R26.2 U1.K2 | length 31.7
  L1 w0.093: v1(22.075,30.38) 22.675,30.38 23.375,31.08 23.375,33.075 23.5,33.2 R26.2@23.5,34.7 R24.1@24.9,34.7 ; v2(23.7,11.6) U1.K2@24.1,11.2
  L2 w0.1: v3(23.4,11.3) v2(23.7,11.6)
  L3 w0.08: v4(22.9,17.2) 22.525,16.825 22.525,16.295 22.23,16 21.5,16 20.9,15.4 20.9,14.485 20.5,14.085 20.5,12.6 21.1,12 21.7,12 22.475,11.225 23.325,11.225 v3(23.4,11.3)
  L10 w0.08: v1(22.075,30.38) 22.075,29.705 21.725,29.355 21.725,28.245 21.945,28.025 22.188,28.025 22.575,27.638 22.575,27.162 22.4,26.987 22.4,26.758 23,26.158 23,25.075 22.525,24.6 22.525,17.845 22.9,17.47 v4(22.9,17.2)
HDMI_HPD: C74.2 J1.43 R21.1 U1.K1 | length 37
  L1 w0.093: v2(23.7,10.8) U1.K1@24.1,10.4 ; R21.1@24.3,31.7 24.75,31.25 v1(24.75,30.955)
  L2 w0.1: v3(23.4,10.5) v2(23.7,10.8)
  L3 w0.08: v4(22.9,16.4) 22.9,15.475 22.525,15.1 22.525,13.7 22.4,13.575 22.4,12.2 22.625,11.975 23.055,11.975 23.215,11.815 23.385,11.815 23.685,11.515 23.685,10.785 v3(23.4,10.5)
  L10 w0.08: v4(22.9,16.4) 22.9,16.67 22.475,17.095 22.475,17.4 22.325,17.55 22.325,24.683 22.8,25.158 22.8,26.075 22.2,26.675 22.2,27.07 22.375,27.245 22.375,27.555 22.155,27.775 21.912,27.775 21.475,28.212 21.475,29.388 21.7,29.613 21.7,31.1 21,31.8 21,32.9 21.492,33.392 22.968,33.392 23.475,33.9 24.3,33.9 24.75,33.45 24.75,32.8 24.5,32.55 24.5,31.85 24.75,31.6 v1(24.75,30.955)
  L12 w0.101: C74.2@23.7,30.2 24.076,30.576 24.371,30.576 v1(24.75,30.955) ; v1(24.75,30.955) J1.43@24.75,32.33
HDMI_RESREF: R30.2 U1.J1 | length 1.3
  L1 w0.3: v1(22.9,10.8) U1.J1@23.3,10.4
  L12 w0.3: v1(22.9,10.8) R30.2@23.6,10.8
I2C1_SCL: J2.14 R47.1 U1.N5 | length 18.6
  L1 w0.093: v2(26.1,13.2) U1.N5@26.5,13.6 ; v1(32.313,6.242) 33.438,6.242 34.563,7.367 34.563,8.055 34.707,8.2 R47.1@35.1,8.2
  L2 w0.1: v2(26.1,13.2) v3(26.4,13.5)
  L3 w0.08: v3(26.4,13.5) 26.525,13.375 26.525,10.088 26.975,9.638 26.975,9.113 27.688,8.4 28.4,8.4 28.9,7.9 29.2,7.9 29.763,7.337 29.763,6.137 30.032,5.867 31.938,5.867 v1(32.313,6.242)
  L12 w0.093: J2.14@32.25,7.67 32.25,6.305 v1(32.313,6.242)
I2C1_SDA: J2.12 R46.1 U1.N6 | length 19.7
  L1 w0.093: v2(26.1,14) U1.N6@26.5,14.4 ; v1(32.75,5.68) 33.438,5.68 34.758,7 R46.1@35.1,7
  L2 w0.1: v2(26.1,14) v3(26.4,14.3)
  L3 w0.08: v3(26.4,14.3) 26.085,13.985 26.085,13.412 26.325,13.172 26.325,10.005 26.775,9.555 26.775,9.03 27.605,8.2 28.3,8.2 28.8,7.7 29.117,7.7 29.563,7.255 29.563,5.993 29.888,5.667 32.737,5.667 v1(32.75,5.68)
  L12 w0.101: v1(32.75,5.68) J2.12@32.75,7.67
I2C2_SCL: J1.36 R28.1 U1.U5 | length 34.9
  L1 w0.093: v1(26.912,36.38) 27.35,36.38 27.875,36.905 27.875,38.255 27.63,38.5 R28.1@27.3,38.5 ; U1.U5@29.7,13.6 v2(30.1,14)
  L2 w0.1: v2(30.1,14) v3(30.4,14.3)
  L3 w0.08: v3(30.4,14.3) 30.4,14.57 31.43,15.6 31.7,15.87 v4(31.7,16)
  L10 w0.08: 30.5,34.08 29.925,33.505 29.925,31.938 30.517,31.346 30.517,30.017 30.075,29.575 30.075,27.279 29.925,27.129 29.925,26.355 29.725,26.155 29.725,25.845 30.1,25.47 30.1,24.5 30.775,23.825 30.775,23.362 30.45,23.037 30.45,16.32 30.77,16 v4(31.7,16)
  L10 w0.101: v1(26.912,36.38) 26.912,36.001 27.584,35.33 28.53,35.33 29.08,35.88 30.2,35.88 30.6,35.48 30.6,34.18 30.5,34.08
  L12 w0.101: J1.36@26.75,38.07 26.75,36.542 v1(26.912,36.38)
I2C2_SDA: J1.38 R29.1 U1.T7 | length 31.8
  L1 w0.093: v1(26.188,36.58) 26.58,36.58 26.755,36.755 27.175,36.755 27.3,36.88 R29.1@27.3,37.3 ; U1.T7@28.9,15.2 v2(29.3,14.8)
  L2 w0.1: v3(29,15.1) v2(29.3,14.8)
  L3 w0.08: v3(29,15.1) 29.7,15.1 30.1,15.5 v4(30.1,15.9)
  L10 w0.08: v1(26.188,36.58) 26.188,36.343 27.53,35 28.62,35 29.2,35.58 30.05,35.58 30.275,35.355 30.275,34.3 29.675,33.7 29.675,31.805 30.217,31.263 30.217,30.092 29.875,29.75 29.875,27.362 29.7,27.187 29.7,26.413 29.508,26.221 29.508,25.7 29.9,25.308 29.9,24.33 30.475,23.755 30.475,23.445 30.15,23.12 30.15,15.95 v4(30.1,15.9)
  L12 w0.093: v1(26.188,36.58) 26.25,36.642 J1.38@26.25,38.07
I2C3_SCL: J2.19 R31.1 R157.2 U1.F21 | length 44.4
  L1 w0.093: U1.F21@20.9,26.4 v2(21.3,26.8) ; v2(34,2.1) 34.5,2.6 R31.1@34.5,2.7 R157.2@35.7,2.7
  L2 w0.1: v3(21,26.5) v2(21.3,26.8) ; v2(34,2.1) v3(34.3,1.8)
  L3 w0.08: v3(21,26.5) v4(21,26.9) ; v4(31.05,1.458) 31.05,1.73 31.5,2.18 31.938,2.18 32.718,1.4 33.9,1.4 v3(34.3,1.8)
  L10 w0.08: v4(21,26.9) 21,26.7 21.675,26.025 21.675,20.7 20.925,19.95 20.925,14.575 21.125,14.375 21.425,14.375 21.525,14.275 21.525,13.762 21.912,13.375 22.1,13.375 22.3,13.175 22.3,12.187 22.493,11.993 22.493,11.476 22.795,11.175 23.725,11.175 24.125,10.775 24.125,10.6 24.3,10.425 25.625,10.425 26,10.8 26.7,10.8 27.4,10.1 27.4,8.4 28.3,7.5 29.022,7.5 29.563,6.96 29.563,5.838 28.925,5.2 28.925,3.313 30.78,1.458 v4(31.05,1.458) 31.05,1.318 v6(30.75,1.018)
  L11 w0.1: v5(30.75,0.617) v6(30.75,1.018)
  L12 w0.093: v5(30.75,0.617) J2.19@30.75,1.93
I2C3_SDA: J2.17 R32.1 R156.2 U1.D24 | length 45.4
  L1 w0.093: v2(18.9,29.2) U1.D24@19.3,28.8 ; v2(33.987,0.808) 34.487,1.308 R32.1@34.487,1.408 R156.2@35.687,1.408
  L2 w0.1: v2(18.9,29.2) v3(19.3,29.2) ; v2(33.987,0.808) v3(34.287,1.107)
  L3 w0.08: v3(19.3,29.2) v4(19.6,28.9) ; v4(31.75,1.758) 32.39,1.118 34.277,1.118 v3(34.287,1.107)
  L10 w0.08: v4(19.6,28.9) 21.375,27.125 21.375,26.695 21.925,26.145 21.925,20.525 21.725,20.325 21.725,16.245 21.3,15.82 21.3,15.33 21.725,14.905 21.725,13.845 21.995,13.575 22.183,13.575 22.5,13.258 22.5,12.27 22.745,12.025 23.005,12.025 23.43,11.6 23.775,11.6 24.2,11.175 26.725,11.175 27.625,10.275 27.625,8.575 28.45,7.75 29.155,7.75 29.813,7.093 29.813,5.643 29.125,4.955 29.125,4.645 29.285,4.485 29.285,3.336 30.788,1.833 31.675,1.833 v4(31.75,1.758) 31.75,1.518 v6(31.25,1.018)
  L11 w0.1: v5(31.25,0.617) v6(31.25,1.018)
  L12 w0.093: v5(31.25,0.617) J2.17@31.25,1.93
I2C4_SCL: J1.35 R45.1 R157.1 U1.E15 | length 154.3
  L1 w0.093: U1.E15@20.1,21.6 v2(20.5,21.2) ; v1(26.813,33.793) 27.412,33.793 27.7,33.505 R45.1@27.7,32.9 ; R157.1@36.7,2.7 v2@37.292,2.7
  L2 w0.1: v2(20.5,21.2) v3(20.8,21.5) ; v3(37.3,2.3) v2(37.3,2.7)
  L3 w0.08: v4(13.9,3.8) 14.775,2.925 15.725,2.925 16.2,3.4 17.325,3.4 17.8,2.925 18.225,2.925 18.559,3.259 19.676,3.259 20.117,3.7 21.983,3.7 22.69,2.993 24.93,2.993 25.312,3.375 26.1,3.375 26.375,3.1 29.283,3.1 29.583,2.8 33.783,2.8 34.041,2.541 34.5,2.541 35.341,1.7 36.4,1.7 37,2.3 v3(37.3,2.3) 37.9,1.7 60.73,1.7 62.715,3.685 62.715,6.815 63.8,7.9 v4(63.8,9.3) ; v2(20.5,21.2) v3(20.8,21.5) ; v1(26.813,33.793) 27.338,33.793 27.74,34.195 29.795,34.195 30.805,35.205 31.625,35.205 31.775,35.355 31.775,35.36 31.995,35.58 32.305,35.58 32.555,35.33 32.945,35.33 33.195,35.58 36.5,35.58 36.87,35.95 37.863,35.95 38.425,36.512 38.425,36.855 38.545,36.975 39,36.975 39.6,37.575 51.055,37.575 51.33,37.3 51.33,36.17 52.4,35.1 62.9,35.1 v4(64,34)
  L10 w0.08: v4(13.9,3.8) 13.9,4.63 13.725,4.805 13.725,7.567 14.1,7.942 14.1,8.5 15.625,10.025 15.625,11.255 15.725,11.355 15.725,14.775 15.525,14.975 15.525,16.155 15.745,16.375 15.975,16.375 16.3,16.7 16.3,18.4 16.075,18.625 16.075,19.505 16.675,20.105 16.675,20.705 17.07,21.1 18.47,21.1 18.745,20.825 20.125,20.825 v2(20.5,21.2) ; v4(63.8,9.3) 64.7,10.2 64.7,14.4 64.375,14.725 64.375,17.3 64.1,17.575 64.1,23.6 64.875,24.375 64.875,33.355 64.23,34 v4(64,34)
  L12 w0.093: J1.35@26.75,32.33 26.75,33.73 v1(26.813,33.793)
  other v4: 20.5,21.2
I2C4_SDA: J1.37 R44.1 R156.1 U1.D16 | length 158.7
  L1 w0.093: U1.D16@19.3,22.4 v2(19.7,22) ; v1(26.288,34.093) 26.363,34.168 27.832,34.168 28.3,33.7 28.3,31.9 28.1,31.7 R44.1@27.7,31.7 ; R156.1@36.687,1.408 v2@37.267,1.408
  L2 w0.1: v3(19.7,21.6) v2(19.7,22) ; v3(36.88,1.395) v2(37.28,1.395)
  L3 w0.08: v4(13.5,4.5) 13.5,3.67 14.445,2.725 15.908,2.725 16.333,3.15 17.192,3.15 17.617,2.725 18.408,2.725 18.692,3.009 19.809,3.009 20.25,3.45 21.83,3.45 22.487,2.793 25.013,2.793 25.395,3.175 25.9,3.175 26.275,2.8 29.2,2.8 29.5,2.5 32.3,2.5 32.4,2.6 33.7,2.6 34,2.3 34.3,2.3 35.205,1.395 v3(36.88,1.395) 60.908,1.395 63.1,3.587 63.1,6.7 64.3,7.9 v4(64.3,8.5) ; v4(19.7,21.2) v3(19.7,21.6) ; v1(26.288,34.093) 26.582,34.093 26.657,34.168 27.38,34.168 27.632,34.42 29.65,34.42 30.685,35.455 31.587,35.455 32.032,35.9 32.268,35.9 32.526,35.643 32.974,35.643 33.232,35.9 36.4,35.9 36.7,36.2 37.83,36.2 38.225,36.595 38.225,36.938 38.462,37.175 38.9,37.175 39.575,37.85 51.163,37.85 51.73,37.283 51.73,36.253 52.483,35.5 63.3,35.5 v4(64,34.8)
  L10 w0.08: v4@13.525,4.5 13.525,7.65 13.775,7.9 13.775,8.475 15.4,10.1 15.4,11.4 15.475,11.475 15.475,14.742 15.325,14.892 15.325,16.855 16.075,17.605 16.075,18.342 15.875,18.542 15.875,19.762 16.475,20.362 16.475,20.788 16.987,21.3 18.3,21.3 18.575,21.575 19.325,21.575 v4(19.7,21.2) ; v4(64,34.8) 64,34.73 65.275,33.455 65.275,24.292 64.5,23.517 64.5,17.658 64.775,17.383 64.775,14.808 65.1,14.483 65.1,9.3 v4(64.3,8.5)
  L12 w0.093: J1.37@26.25,32.33 26.25,34.055 v1(26.288,34.093)
JTAG_MOD: R61.2 U1.H6 | length 2.4
  L1 w0.3: v1(22.1,14) U1.H6@22.5,14.4
  L12 w0.3: R61.2@22,12.2 22.1,12.3 v1(22.1,14)
JTAG_NTRST: J2.41 R62.1 U1.C2 | length 16.2
  L1 w0.093: U1.C2@18.5,11.2 18.9,10.8 20.3,10.8 20.5,11 20.5,11.4 20.7,11.6 v2(21.3,11.6) ; v1(25.25,3.968) 25.3,3.918 R62.1@25.3,2.6
  L2 w0.1: v2(21.3,11.6) v3(21.6,11.3)
  L3 w0.08: v3(21.6,11.3) v4(22.1,10.8)
  L10 w0.08: v4(22.1,10.8) 22.1,10.179 22.725,9.554 22.725,8.767 25.238,6.255 25.238,3.981 v1(25.25,3.968)
  L12 w0.093: J2.41@25.25,1.93 v1(25.25,3.968)
JTAG_TCK: J2.43 R92.2 | length 3.9
  L1 w0.093: v1(24.75,3.368) 24.75,1.55 24.9,1.4 R92.2@25.3,1.4
  L12 w0.093: J2.43@24.75,1.93 v1(24.75,3.368)
JTAG_TCK_R: R92.1 U1.H5 | length 20.7
  L1 w0.093: v2(22.1,13.2) U1.H5@22.5,13.6 ; v2(25.8,2) 26.3,1.5 R92.1@26.3,1.4
  L2 w0.1: v3(21.8,13.5) v2(22.1,13.2) ; v2(25.8,2) v3(25.8,2.4)
  L3 w0.08: v3(21.8,13.5) 21.9,13.4 v4(21.9,13) ; v4(25.55,2.8) 25.55,2.65 v3(25.8,2.4)
  L10 w0.08: v4(21.9,13) 22,12.9 22,11.613 22.475,11.138 22.475,10.695 22.77,10.4 23.925,10.4 24.075,10.25 24.075,10 23.925,9.85 23.3,9.85 23.15,9.7 23.15,9.45 23.3,9.3 24.1,9.3 24.25,9.15 24.25,8.9 24.1,8.75 23.65,8.75 23.5,8.6 23.5,8.35 23.65,8.2 23.855,8.2 24.855,7.2 25.8,7.2 25.95,7.05 25.95,6.8 25.794,6.644 25.594,6.644 25.438,6.488 25.438,6.238 25.594,6.083 25.594,5.7 25.494,5.6 25.494,5.306 25.6,5.2 26,5.2 26.15,5.05 26.15,4.8 26,4.65 25.65,4.65 25.5,4.5 25.5,4.25 25.665,4.085 25.665,3.6 25.334,3.269 25.325,3.269 25.325,3.025 v4(25.55,2.8)
JTAG_TDI: J2.47 R90.2 | length 2.3
  L1 w0.093: v1(23.75,3.368) 23.75,2.75 R90.2@23.9,2.6
  L12 w0.093: J2.47@23.75,1.93 v1(23.75,3.368)
JTAG_TDI_R: R63.1 R90.1 U1.G5 | length 20.9
  L1 w0.093: v2(21.1,2) 21.6,1.5 R63.1@21.6,1.4 22,1.4 22.1,1.5 22.1,2.2 22.5,2.6 R90.1@22.9,2.6 ; v2(21.3,13.2) U1.G5@21.7,13.6
  L2 w0.1: v3(21,13.5) v2(21.3,13.2) ; v2(21.1,2) v3(21.1,2.4)
  L3 w0.08: v3(21,13.5) 21,13.1 v4(21.1,13) ; v3(21.1,2.4) v4(21.1,2.8)
  L10 w0.08: v4(21.1,2.8) 21.42,2.8 21.795,3.175 23.325,3.175 23.507,2.993 24.125,2.993 24.313,3.18 24.313,3.5 24.625,3.813 24.625,4.367 24.838,4.579 24.838,5.262 24.677,5.423 24.677,6.15 22.325,8.502 22.325,9.388 21.984,9.729 21.841,9.729 20.925,10.645 20.925,11.295 21.175,11.545 21.175,11.995 20.925,12.245 20.925,12.825 v4(21.1,13)
JTAG_TDO: J2.45 R161.2 | length 5.2
  L1 w0.093: R161.2@23.9,1.4 24.3,1.4 24.5,1.6 24.5,3.088 24.25,3.338 v1(24.25,3.968)
  L12 w0.093: J2.45@24.25,1.93 v1(24.25,3.968)
JTAG_TDO_R: R161.1 U1.G6 | length 19.4
  L1 w0.093: v2(21.3,14) U1.G6@21.7,14.4 ; v2(22.4,2) 22.9,1.5 R161.1@22.9,1.4
  L2 w0.1: v2(21.3,14) v3(21.6,14.3) ; v2(22.4,2) v3(22.4,2.4)
  L3 w0.08: v4(21.1,14) 21.4,14.3 v3(21.6,14.3) ; v4(21.95,2.8) 22,2.8 v3(22.4,2.4)
  L10 w0.08: v4(21.1,14) 21.1,13.755 21.525,13.33 21.525,12.705 21.675,12.555 21.675,10.321 22.525,9.471 22.525,8.635 24.95,6.21 24.95,5.433 25.038,5.345 25.038,4.496 24.875,4.334 24.875,3.773 25.125,3.523 25.125,3.205 24.712,2.793 v4@21.95,2.793
JTAG_TMS: J2.49 R64.1 U1.C3 | length 18.8
  L1 w0.093: U1.C3@18.5,12 18.9,11.6 20.3,11.6 20.5,11.8 v2(20.5,12.4) ; R64.1@21.6,2.6 22,2.6 22.3,2.9 22.3,3.6 22.668,3.968 v1(23.25,3.968)
  L2 w0.1: v3(20.5,12) v2(20.5,12.4)
  L3 w0.08: v3(20.5,12) v4(20.8,11.7)
  L10 w0.08: v4(20.8,11.7) 20.725,11.625 20.725,10.462 21.658,9.529 21.859,9.529 22.125,9.263 22.125,8.369 24.394,6.1 24.394,5.306 24.638,5.062 24.638,4.662 24.405,4.43 23.712,4.43 v1(23.25,3.968)
  L12 w0.093: J2.49@23.25,1.93 v1(23.25,3.968)
LED1: R82.1 R94.1 U8.17 | length 10.5
  L1 w0.093: U8.17@13.25,38.49 v2(13.25,39.1) ; v2(19.975,39.08) 19.975,39.05 R94.1@20.525,38.5 R82.1@21.5,38.5
  L2 w0.1: v3(13.25,38.7) v2(13.25,39.1) ; v3(19.975,38.68) v2(19.975,39.08)
  L3 w0.08: v3(13.25,38.7) 13.535,38.415 14.368,38.415 14.503,38.55 17.15,38.55 17.4,38.8 18.287,38.8 18.662,38.425 19.138,38.425 19.413,38.7 v3@19.975,38.7
LED2: R81.1 R102.2 U8.15 | length 14.2
  L1 w0.093: U8.15@14.25,38.49 v2(14.25,39.1) ; R102.2@25.2,37.3 R81.1@25.2,38.5 v2(25.2,39.1)
  L2 w0.1: v3(14.25,38.7) v2(14.25,39.1) ; v3(24.8,39.1) v2(25.2,39.1)
  L3 w0.08: v3(14.25,38.7) 14.35,38.8 17.1,38.8 17.3,39 18.37,39 18.745,38.625 19.055,38.625 19.415,38.985 24.685,38.985 v3(24.8,39.1)
LGATE1_2V5: Q6.4 U13.18 | length 16.2
  L1 w0.5: v1(62.1,30.4) 62.995,30.4 Q6.4@63,30.395
  L3 w0.5: 68.7,22 v1(68.9,21.8)
  L3 w0.6: 62.1,30.1 v1(62.1,30.4) ; 64.3,23.2 65.2,22.3 68.4,22.3 68.7,22
  L3 w0.8: 62.1,30.1 62.1,25.4 64.3,23.2
  L12 w0.2: U13.18@67.1,21.25 68.05,21.25 68.2,21.4
  L12 w0.3: 68.2,21.4 68.3,21.5
  L12 w0.4: 68.3,21.5 68.6,21.8 v1(68.9,21.8)
LGATE1_3V3: Q3.4 U11.18 | length 18.2
  L1 w0.5: v1(6.1,9.6) 6.995,9.6 Q3.4@7,9.605
  L3 w0.6: v1(1.6,19) 2,18.6 ; 5.8,9.3 v1(6.1,9.6)
  L3 w0.8: 2,18.6 2.6,18 4.4,18 5.4,17 5.4,15.5 3.4,13.5 3.4,9.9 4.3,9 5.5,9 5.8,9.3
  L12 w0.2: v1(1.6,19) 2.1,19 2.35,18.75 U11.18@2.9,18.75
LGATE2_1V5: Q7.4 U13.23 | length 11
  L1 w0.5: v1(67.7,9.6) 68.595,9.6 Q7.4@68.6,9.605
  L3 w0.5: 67.7,18.4 67.7,18.6 v1(67.9,18.8)
  L3 w0.6: v1(67.7,9.6) 67.7,9.9
  L3 w0.8: 67.7,9.9 67.7,18.4
  L12 w0.2: U13.23@67.1,18.75 67.85,18.75 v1(67.9,18.8)
LGATE2_1V375: Q4.4 U11.23 | length 11.2
  L1 w0.5: Q4.4@1.4,30.395 v1@2.295,30.395
  L3 w0.6: 1.9,21.7 v1(2.2,21.4) ; 2.3,30 v1(2.3,30.4)
  L3 w0.8: 1.9,21.7 1.575,22.025 1.575,27.975 2.3,28.7 2.3,30
  L12 w0.2: v1(2.2,21.4) 2.35,21.25 U11.23@2.9,21.25
LVDS0_CABC: J2.6 R33.1 U1.A17 | length 46.6
  L1 w0.093: U1.A17@16.9,23.2 v2(17.3,22.8) ; v1(34.25,5.68) 34.82,5.68 35,5.5 R33.1@35,5.1
  L2 w0.1: v3(17,22.5) v2(17.3,22.8)
  L3 w0.08: v4(12.9,7.1) 12.9,7.3 13.65,8.05 14.633,8.05 15.517,7.166 15.517,6.408 15.8,6.125 16.875,6.125 17.55,5.45 17.892,5.45 18.167,5.725 18.925,5.725 19.2,6 20.2,6 20.4,5.8 21.083,5.8 21.183,5.7 22.219,5.7 22.489,5.43 25.596,5.43 25.853,5.173 26.105,5.173 26.344,5.412 26.825,5.412 27.12,5.118 28.954,5.118 29.212,5.375 29.833,5.375 30.158,5.05 30.687,5.05 31.012,5.375 31.65,5.375 31.9,5.125 33.282,5.125 33.838,5.68 v1(34.25,5.68) ; v3(17,22.5) v4(17.3,22.2)
  L10 w0.08: v4(12.9,7.1) 12.9,7.67 13.275,8.045 13.275,8.975 14.7,10.4 14.7,17.07 15.119,17.489 15.119,18.132 15.3,18.313 15.3,20.53 15.87,21.1 16.221,21.1 17.3,22.179 v4(17.3,22.2)
  L12 w0.093: v1(34.25,5.68) J2.6@34.25,7.67
LVDS0_CLK_N: J2.13 U1.V4 | length 17.5
  L1 w0.09: U1.V4@30.5,12.8 v2(30.9,12.4)
  L2 w0.1: v3(30.6,12.7) v2(30.9,12.4)
  L3 w0.085: v4(30.3,12.4) v3(30.6,12.7)
  L10 w0.085: v4(30.3,12.4) 29.62,11.72 29.62,10.42 29.4,10.2 28.804,10.2 28.368,9.763 28.368,9.032 28.868,8.532 30.168,8.532 30.6,8.1 30.6,4.956 30,4.356 30,3.6 30.708,2.892 32,2.892 v6(32.05,2.843)
  L11 w0.1: v6(32.05,2.843) 32.05,3.043 v5(32.25,3.243)
  L12 w0.09: J2.13@32.25,1.93 v5(32.25,3.243)
LVDS0_CLK_P: J2.15 U1.V3 | length 17.5
  L1 w0.09: U1.V3@30.5,12 v2(30.9,11.6)
  L2 w0.1: v3(30.6,11.9) v2(30.9,11.6)
  L3 w0.085: v3(30.6,11.9) v4(30.9,12.2)
  L10 w0.085: v4(30.9,12.2) 30.754,12.2 30.492,11.938 30.233,11.938 29.9,11.604 29.9,10.304 29.516,9.92 28.92,9.92 28.648,9.648 28.648,9.148 28.983,8.812 30.283,8.812 30.88,8.216 30.88,4.84 30.28,4.24 30.28,3.716 30.823,3.172 31.85,3.172 31.95,3.273 v6(31.95,3.643)
  L11 w0.1: v5(31.75,3.243) 31.95,3.443 v6(31.95,3.643)
  L12 w0.09: J2.15@31.75,1.93 v5(31.75,3.243)
LVDS0_PWM: J2.5 U1.F18 | length 52.6
  L1 w0.093: v2(20.5,23.6) U1.F18@20.9,24
  L2 w0.1: v3(20.1,23.3) 20.4,23.6 v2(20.5,23.6)
  L3 w0.08: v4(13.1,6.3) 13.275,6.475 13.275,7.175 13.9,7.8 14.55,7.8 15.317,7.033 15.317,6.225 15.617,5.925 16.742,5.925 17.467,5.2 17.975,5.2 18.3,5.525 19.008,5.525 19.283,5.8 20.117,5.8 20.317,5.6 21,5.6 21.2,5.4 22.136,5.4 22.356,5.18 25.467,5.18 25.747,4.9 26.115,4.9 26.395,5.18 26.724,5.18 27.037,4.868 29.037,4.868 29.345,5.175 29.7,5.175 30.075,4.8 30.77,4.8 31.145,5.175 31.505,5.175 31.805,4.875 32.938,4.875 33.383,4.43 34.225,4.43 v1(34.25,4.455) ; v3(20.1,23.3) 20.1,23.1 v4(20.4,22.8)
  L10 w0.08: v4(13.1,6.3) 13.275,6.475 13.275,7.762 13.475,7.962 13.475,8.892 14.9,10.317 14.9,16.987 15.319,17.406 15.319,18.049 15.5,18.23 15.5,20 15.7,20.2 16.03,20.2 16.275,20.445 16.275,20.871 17.004,21.6 18.23,21.6 18.525,21.895 18.525,22.155 18.745,22.375 19.1,22.375 19.85,21.625 20.655,21.625 20.9,21.87 20.9,22.3 v4(20.4,22.8)
  L12 w0.093: J2.5@34.25,1.93 v1(34.25,4.455)
LVDS0_TX0_N: J2.2 U1.U2 | length 17.4
  L1 w0.09: v2(29.3,11.6) U1.U2@29.7,11.2
  L2 w0.1: v3(29,11.3) v2(29.3,11.6)
  L3 w0.085: v4(28.6,10.9) v3(29,11.3)
  L10 w0.085: v4(28.6,10.9) 28.783,11.082 28.783,11.363 28.868,11.448 28.868,11.752 28.52,12.1 28.52,13.036 29.117,13.632 29.452,13.632 30.492,14.672 31.944,14.672 33.28,13.336 33.28,13.02 33.733,12.568 33.733,11.383 35.048,10.068 35.048,8.911 34.85,8.713 v6(34.85,8.582)
  L11 w0.1: v6(34.85,8.582) v5(35.25,8.982)
  L12 w0.09: J2.2@35.25,7.67 v5(35.25,8.982)
LVDS0_TX0_P: J2.4 U1.U1 | length 17.4
  L1 w0.09: v2(29.3,10.8) U1.U1@29.7,10.4
  L2 w0.1: v2(29.3,10.8) v3(29.6,11.1)
  L3 w0.085: v4(29.2,10.7) v3(29.6,11.1)
  L10 w0.085: v4(29.2,10.7) 29.063,10.837 29.063,11.247 29.148,11.332 29.148,11.868 28.8,12.216 28.8,12.92 29.233,13.352 29.568,13.352 30.608,14.392 31.828,14.392 32.12,14.1 32.12,13.9 31.96,13.74 31.96,13.6 32.07,13.49 32.21,13.49 32.37,13.65 32.57,13.65 33,13.22 33,12.904 33.453,12.452 33.453,11.267 34.768,9.952 34.768,9.027 34.35,8.609 v6(34.35,8.582)
  L11 w0.1: v6(34.35,8.582) v5(34.75,8.982)
  L12 w0.09: J2.4@34.75,7.67 v5(34.75,8.982)
LVDS0_TX1_N: J2.8 U1.U4 | length 17.4
  L1 w0.09: U1.U4@29.7,12.8 v2(30.1,13.2)
  L2 w0.1: v3(29.8,12.9) v2(30.1,13.2)
  L3 w0.085: v4(29.3,12.9) 29.4,12.8 29.7,12.8 v3(29.8,12.9)
  L10 w0.085: v4(29.3,12.9) 29.303,12.903 29.687,12.903 29.964,13.18 31.368,13.18 32.932,11.616 32.932,11.068 33.548,10.452 33.548,9.368 33.9,9.016 33.9,8.38 34.242,8.038 35.162,8.038 35.7,7.5 35.7,6.254 35.296,5.85 34.684,5.85 34.28,6.254 34.28,6.52 34.042,6.758 v6(33.75,6.758)
  L11 w0.1: v5(33.75,6.358) v6(33.75,6.758)
  L12 w0.09: v5(33.75,6.358) J2.8@33.75,7.67
LVDS0_TX1_P: J2.10 U1.U3 | length 17.4
  L1 w0.09: U1.U3@29.7,12 v2(30.1,12.4)
  L2 w0.1: v3(29.8,12.1) v2(30.1,12.4)
  L3 w0.085: v4(29.3,12.3) 29.6,12.3 v3(29.8,12.1)
  L10 w0.085: v4(29.3,12.3) 29.354,12.3 29.677,12.623 29.803,12.623 30.08,12.9 31.252,12.9 32.652,11.5 32.652,10.952 33.268,10.337 33.268,9.252 33.62,8.9 33.62,8.264 34.126,7.758 35.046,7.758 35.42,7.384 35.42,6.37 35.18,6.13 34.8,6.13 34.56,6.37 34.56,6.636 34.158,7.038 33.997,7.038 33.904,7.13 33.43,7.13 33.25,6.95 v6(33.25,6.758)
  L11 w0.1: v5(33.25,6.358) v6(33.25,6.758)
  L12 w0.09: v5(33.25,6.358) J2.10@33.25,7.67
LVDS0_TX2_N: J2.1 U1.V2 | length 17.4
  L1 w0.09: U1.V2@30.5,11.2 v2(30.9,10.8)
  L2 w0.1: v3(30.6,11.1) v2(30.9,10.8)
  L3 w0.085: v4(30.3,10.8) v3(30.6,11.1)
  L10 w0.085: v4(30.3,10.8) 30.892,10.8 31.276,10.416 31.276,9.878 31.398,9.757 31.398,8.898 31.945,8.351 31.945,6.071 32.3,5.716 32.3,5.152 31.948,4.8 31.948,4.6 32.508,4.04 32.508,3.841 32.815,3.533 32.815,2.781 33.131,2.465 35.435,2.465 35.8,2.1 35.8,1.567 v6(35.25,1.017)
  L11 w0.1: v5(35.25,0.617) v6(35.25,1.017)
  L12 w0.09: v5(35.25,0.617) J2.1@35.25,1.93
LVDS0_TX2_P: J2.3 U1.V1 | length 17.4
  L1 w0.09: U1.V1@30.5,10.4 v2(30.9,10)
  L2 w0.1: v3(30.6,10.3) v2(30.9,10)
  L3 w0.085: v4(30.3,10) v3(30.6,10.3)
  L10 w0.085: v4(30.3,10) 30.3,10.146 30.674,10.52 30.776,10.52 30.996,10.3 30.996,9.762 31.118,9.641 31.118,8.782 31.665,8.235 31.665,5.955 32.02,5.6 32.02,5.268 31.668,4.916 31.668,4.484 32.228,3.924 32.228,3.725 32.535,3.418 32.535,2.665 33.015,2.185 35.319,2.185 35.52,1.984 35.52,1.683 35.227,1.39 35.096,1.39 34.75,1.044 v6(34.75,1.017)
  L11 w0.1: v5(34.75,0.617) v6(34.75,1.017)
  L12 w0.09: v5(34.75,0.617) J2.3@34.75,1.93
LVDS0_TX3_N: J2.7 U1.W2 | length 17.4
  L1 w0.09: U1.W2@31.3,11.2 v4(31.7,10.8)
  L2 w0.1: v3(31.4,11.1) v4(31.7,10.8)
  L3 w0.085: v3(31.4,11.1) v4(31.7,10.8)
  L10 w0.085: v4(31.7,10.8) 31.882,10.618 32.178,10.618 32.532,10.263 32.532,9.168 32.968,8.733 32.968,6.443 34.098,5.312 34.483,5.312 34.9,4.896 35.449,4.896 35.913,4.432 36.568,4.432 36.98,4.02 36.98,3.484 36.516,3.02 35.68,3.02 35.057,3.643 v6(33.75,3.643)
  L11 w0.1: v5(33.75,3.243) v6(33.75,3.643)
  L12 w0.09: J2.7@33.75,1.93 v5(33.75,3.243)
  other v2: 31.7,10.8
LVDS0_TX3_P: J2.9 U1.W1 | length 17.4
  L1 w0.09: U1.W1@31.3,10.4 v4(31.7,10)
  L2 w0.1: v3(31.4,10.3) v4(31.7,10)
  L3 w0.085: v3(31.4,10.3) v4(31.7,10)
  L10 w0.085: v4(31.7,10) 31.7,10.237 31.8,10.338 32.062,10.338 32.252,10.148 32.252,9.053 32.688,8.617 32.688,6.327 33.982,5.032 34.368,5.032 34.784,4.616 35.333,4.616 35.797,4.152 36.452,4.152 36.7,3.904 36.7,3.6 36.4,3.3 35.796,3.3 35.173,3.923 33.997,3.923 33.904,4.015 33.596,4.015 33.25,3.669 v6(33.25,3.643)
  L11 w0.1: v5(33.25,3.243) v6(33.25,3.643)
  L12 w0.09: J2.9@33.25,1.93 v5(33.25,3.243)
  other v2: 31.7,10
NetC88_1: C88.1 U6.4 | length 2.1
  L12 w0.4: C88.1@61.4,7.8 62.4,7.8 62.75,8.15 U6.4@62.75,8.75
NetC211_2: C211.2 R122.1 | length 1
  L12 w0.4: C211.2@1.4,16.4 1.4,17.3 R122.1@1.5,17.4
NetC212_1: C212.1 R121.2 | length 1.1
  L12 w0.4: C212.1@1.3,23.8 1.3,22.8 R121.2@1.4,22.7
NetC230_2: C230.2 R145.1 | length 1.1
  L12 w0.4: R145.1@68.4,23.5 68.5,23.6 C230.2@68.5,24.6
NetC231_1: C231.1 R146.2 | length 1.2
  L12 w0.4: R146.2@68.6,17.3 68.7,17.2 C231.1@68.7,16.1
NetD2_1: D2.1 Q1.3 | length 2
  L1 w0.093: D2.1@8.7,1.3 v1(9.6,1.3)
  L12 w0.093: Q1.3@9.45,2.3 9.6,2.15 v1(9.6,1.3)
NetD2_2: D2.2 R113.1 | length 2.9
  L1 w0.093: D2.2@8.7,2.9 9.4,2.9 v1(9.6,3.1)
  L12 w0.093: R113.1@8.5,4.4 8.5,3.9 9,3.4 9.3,3.4 v1(9.6,3.1)
NetD3_1: D3.1 Q2.3 | length 2.8
  L1 w0.093: D3.1@27.7,2.7 28.3,2.7 28.5,2.5 28.5,2.1 28.75,1.85 Q2.3@29.9,1.85
NetD3_2: D3.2 R114.1 | length 4.5
  L1 w0.093: D3.2@27.7,1.1 30.983,1.1 31.283,1.4 R114.1@32.1,1.4
NetQ5_1: Q5.1 Q8.3 R131.1 | length 5
  L12 w0.093: Q5.1@1.75,13.95 2.55,13.95 3.65,12.85 Q8.3@3.65,11.9 4.4,11.9 4.8,12.3 R131.1@4.8,12.7
NetR106_1: R106.1 U12.8 | length 1.4
  L1 w0.093: v1(10.8,4.9) 10.9,5 U12.8@10.9,5.45
  L12 w0.093: v1(10.8,4.9) 10.9,4.8 R106.1@10.9,4.2 R106.1@10.9,4.1
NetR109_2: R109.2 U10.7 | length 3
  L1 w0.093: U10.7@28.05,7.035 28.645,7.035 29.063,6.618 30.218,6.618 30.4,6.8 R109.2@30.4,7.2
NetR110_1: R110.1 U10.3 | length 2.5
  L1 w0.093: R110.1@21.3,7.4 21.3,7 21.813,6.487 21.813,5.987 22.035,5.765 U10.3@22.55,5.765
NetR121_1: R121.1 U11.24 | length 1.6
  L12 w0.2: R121.1@1.4,21.7 1.8,21.7 2,21.9 2.301,21.9 2.451,21.75 U11.24@2.9,21.75
NetR122_2: R122.2 U11.17 | length 2.1
  L12 w0.2: U11.17@2.9,18.25 2.275,18.25 2.125,18.4 ; 2.125,18.4 R122.2@1.5,18.4 2.125,18.4
NetR124_1: R124.1 U11.31 | length 1.5
  L12 w0.2: R124.1@6.2,23.8 6.55,23.45 U11.31@6.55,22.4
NetR125_2: R125.2 U11.12 | length 1.9
  L12 w0.2: R125.2@4.9,16 4.9,16.3 5.55,16.95 U11.12@5.55,17.6
NetR128_1: R128.1 R133.2 U11.2 | length 7.5
  L10 w0.08: v6(8.5,21.575) 8.5,21.9 8.9,22.3 v6(8.9,24.6)
  L11 w0.1: v5(8.2,21.275) v6(8.5,21.575) ; v6(8.9,24.6) v5(8.9,25)
  L12 w0.093: U11.2@7.7,21.25 v5@8.25,21.25 ; v5(8.9,25) R133.2@9.4,25 10,25.6 10.8,25.6 10.9,25.5 R128.1@11.5,25.5
NetR145_2: R145.2 U13.17 | length 1.6
  L12 w0.2: U13.17@67.1,21.75 67.65,21.75 R145.2@68.4,22.5
NetR146_1: R146.1 U13.24 | length 1.5
  L12 w0.2: U13.24@67.1,18.25 68.55,18.25 R146.1@68.6,18.3
NetR148_1: R148.1 U13.31 | length 1.6
  L12 w0.2: U13.31@63.45,17.6 63.45,16.05 R148.1@63.5,16
NetR149_2: R149.2 U13.12 | length 1.7
  L12 w0.2: U13.12@64.45,22.4 64.45,23.45 R149.2@64.9,23.9
NetR152_1: R152.1 R155.2 U13.2 | length 6.5
  L12 w0.093: R152.1@57.9,15.9 58.5,15.9 58.6,16 R155.2@59,16 59,17.5 59.4,17.9 61,17.9 61.85,18.75 U13.2@62.3,18.75
ON_5V_LDO: R127.1 U11.4 | length 5.6
  L12 w0.093: U11.4@7.7,20.25 8.45,20.25 9.7,21.5 11.5,21.5 11.8,21.8 12,21.8 12.2,22 R127.1@12.2,22.4
ON_5V_LDO_2: R151.1 U13.4 | length 4.2
  L12 w0.093: R151.1@58.2,19.6 58.9,19.6 59,19.5 61.35,19.5 61.6,19.75 U13.4@62.3,19.75
ON_OFF: J1.6 R48.1 U1.D12 | length 84.9
  L1 w0.093: U1.D12@19.3,19.2 v2(19.7,19.6)
  L2 w0.1: v2(19.7,19.6) v3(20,19.9)
  L3 w0.08: v1(4.8,10.6) 5.5,11.3 5.5,13.87 7.7,16.07 8,16.07 9.255,17.325 10.7,17.325 11,17.625 11,18.33 11.345,18.675 12.326,18.675 13.151,19.5 15.634,19.5 15.934,19.8 18.287,19.8 18.662,20.175 19.725,20.175 v3(20,19.9) ; v4(15.5,37.1) 15.7,37.1 16.422,36.378 17.022,36.378 17.175,36.225 17.175,36.095 17.445,35.825 17.755,35.825 17.93,36 19.6,36 19.955,36.355 21.782,36.355 22.032,36.105 23.005,36.105 23.496,36.596 23.85,36.596 24.349,37.095 25.581,37.095 25.841,37.355 28.555,37.355 29.585,38.385 30.418,38.385 30.585,38.218 30.585,38.215 30.7,38.1 34.092,38.1 v4(34.25,37.943)
  L10 w0.08: v1(4.8,10.6) 4.8,11.2 4.4,11.6 4.4,12.5 3.825,13.075 3.825,18.695 4.275,19.145 4.275,19.55 4,19.825 4,21.7 4.75,22.45 4.75,23.468 4.38,23.838 4.38,24.3 3,25.68 3,29.4 3.725,30.125 3.725,31.325 4.6,32.2 4.6,33.371 7.329,36.1 7.63,36.1 8.83,37.3 9.083,37.3 9.758,37.975 14.625,37.975 v4(15.5,37.1) ; v4(34.25,37.943) v6(34.25,38.982)
  L11 w0.1: v6(34.25,38.982) v5(34.25,39.383)
  L12 w0.093: v1(4.8,10.6) R48.1@5.4,10 ; J1.6@34.25,38.07 v5(34.25,39.383)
